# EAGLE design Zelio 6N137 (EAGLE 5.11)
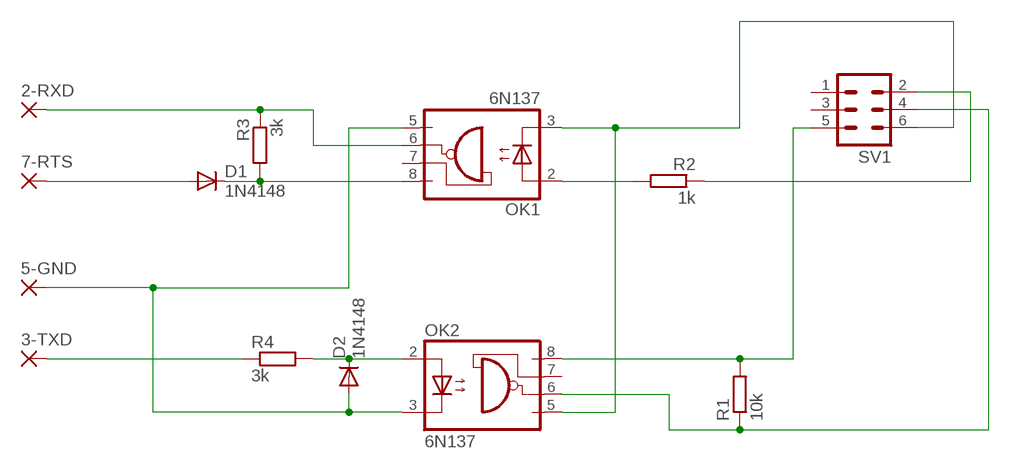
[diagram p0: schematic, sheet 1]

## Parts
2-RXD  2,54/1,0  [2,54/1,0]
3-TXD  2,54/1,0  [2,54/1,0]
5-GND  2,54/1,0  [2,54/1,0]
7-RTS  2,54/1,0  [2,54/1,0]
D1  1N4148  1N4148DO35-7  [DO35-7]
D2  1N4148  1N4148DO35-7  [DO35-7]
OK1  6N137  [DIL08]
OK2  6N137  [DIL08]
R1  10k  R-EU_0204/7  [0204/7]
R2  1k  R-EU_0204/7  [0204/7]
R3  3k  R-EU_0204/7  [0204/7]
R4  3k  R-EU_0204/7  [0204/7]
SV1  MA03-2  [MA03-2]

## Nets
N$1: OK2.8(VCC) R1.2 SV1.5
N$2: 3-TXD.1(P) R4.1
N$3: D2.C OK2.2(A) R4.2
N$4: 5-GND.1(P) D2.A OK1.5(GND) OK2.3(C)
N$5: 2-RXD.1(P) OK1.6(VO) R3.1
N$6: 7-RTS.1(P) D1.A
N$7: D1.C OK1.8(VCC) R3.2
N$8: OK1.2(A) R2.2
N$9: OK2.6(VO) R1.1 SV1.4
N$10: OK1.3(C) OK2.5(GND) SV1.6
N$11: R2.1 SV1.2
Unconnected: OK1.7(VE) OK2.7(VE) SV1.1 SV1.3

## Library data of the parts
2-RXD 3-TXD 5-GND 7-RTS = wirepad:2,54/1,0: THROUGH-HOLE PAD
D1 D2 = diode:1N4148: DIODE
OK1 OK2 = optocoupler:6N137: MOTOROLA OPTO COUPLER; MPN: 6N137; OC_FARNELL: 1328376; OC_NEWARK: 52M1895
R1-R4 = rcl:R-EU_: RESISTOR, European symbol
SV1 = con-lstb:MA03-2: PIN HEADER; OC_FARNELL: unknown; OC_NEWARK: unknown

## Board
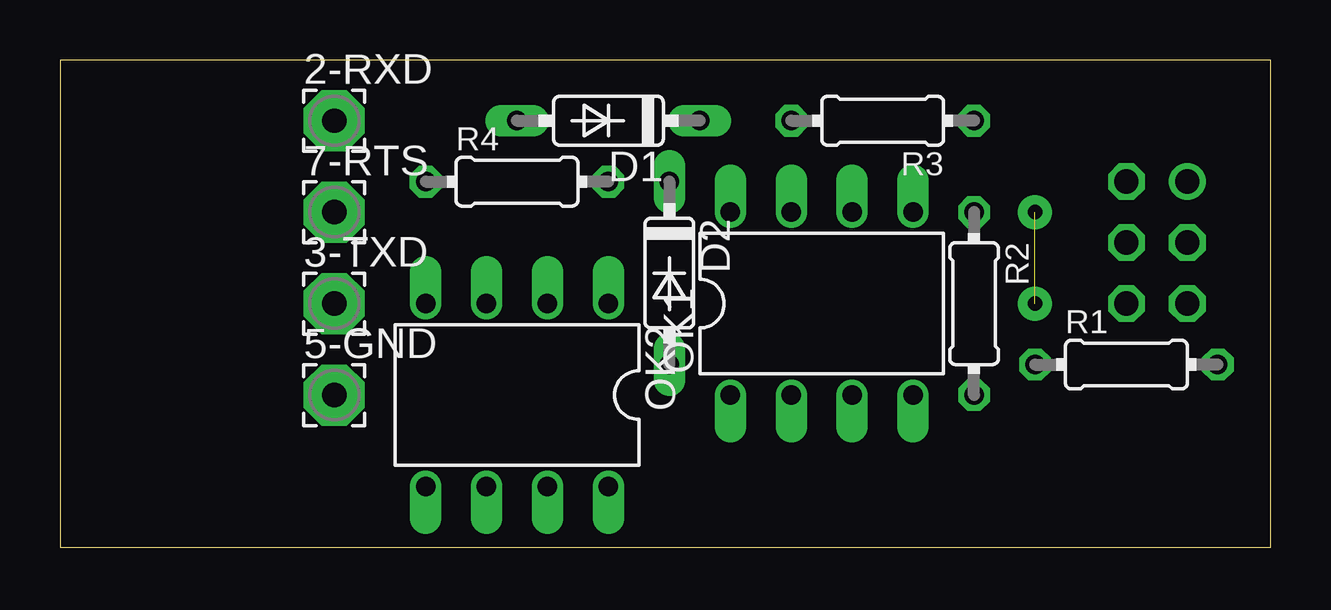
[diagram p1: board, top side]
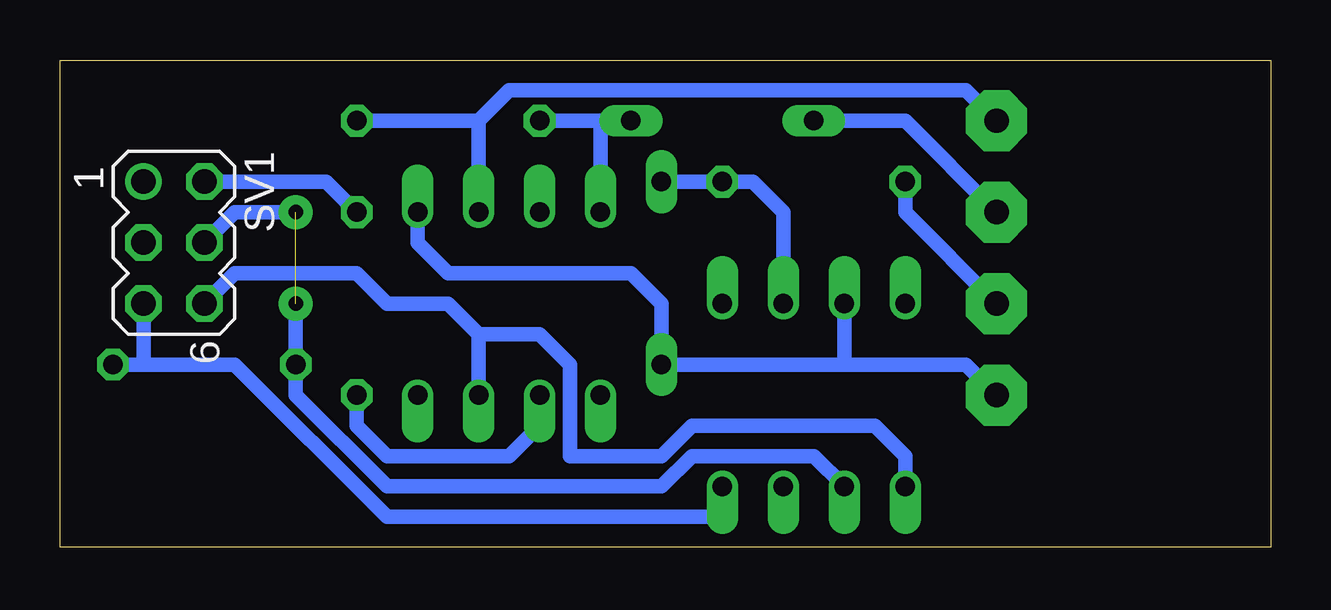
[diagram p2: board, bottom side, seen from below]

Size 50.47 x 20.31 mm. Coordinates in mm from the lower left corner, seen from the top.
Outline: 0,0 50.47,0 50.47,20.31 0,20.31 0,0
Copper layers (1*16): Top 0.035mm / dielectric 1.5mm / Bottom 0.035mm
Design rules "default": minimum track width 10mil, minimum drill 24mil, track to track 8mil, track to pad 8mil, pad to pad 8mil, via to via 8mil, smd to smd 8mil, copper to edge 40mil, drill to drill 8mil, minimum pad ring 10mil, minimum via ring 8mil, stop-mask expansion 4mil, vias tented up to drill 0mil, thermal gap 10mil

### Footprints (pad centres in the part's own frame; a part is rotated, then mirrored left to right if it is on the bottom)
2,54/1,0 = drill 1.016 pad 2.54 octagon: 1 0,0
DO35-7 = drill 0.813 long: A 3.81,0; C -3.81,0
DIL08 = drill 0.813 offset: 1 -3.81,-3.81; 2 -1.27,-3.81; 3 1.27,-3.81; 4 3.81,-3.81; 5 3.81,3.81; 6 1.27,3.81; 7 -1.27,3.81; 8 -3.81,3.81
0204/7 = drill 0.813 octagon: 1 -3.81,0; 2 3.81,0
MA03-2 = drill 1.016 round: 1 -2.54,-1.27 | drill 1.016 octagon: 2 -2.54,1.27; 3 0,-1.27; 4 0,1.27; 5 2.54,-1.27; 6 2.54,1.27

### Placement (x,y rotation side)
2-RXD  11.43,17.78 0 top
3-TXD  11.43,10.16 0 top
5-GND  11.43,6.35 0 top
7-RTS  11.43,13.97 0 top
D1  22.86,17.78 180 top
D2  25.4,11.43 270 top
OK1  31.75,10.16 0 top
OK2  19.05,6.35 180 top
R1  44.45,7.62 0 top
R2  38.1,10.16 270 top
R3  34.29,17.78 180 top
R4  19.05,15.24 0 top
SV1  45.72,12.7 270 bottom

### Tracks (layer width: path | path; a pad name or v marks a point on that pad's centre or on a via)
N$1
  Bottom 0.61: 46.99,7.62 R1.2 | 46.99,7.62 SV1.5 | 46.99,7.62 43.18,7.62 36.83,1.27 22.86,1.27 OK2.8
N$2
  Bottom 0.61: R4.1 15.24,13.97 3-TXD.1
N$3
  Bottom 0.61: D2.C R4.2 21.59,15.24 20.32,13.97 OK2.2
N$4
  Bottom 0.61: OK1.5 35.56,12.7 34.29,11.43 26.67,11.43 25.4,10.16 D2.A 17.78,7.62 | 17.78,7.62 OK2.3 | 5-GND.1 12.7,7.62 17.78,7.62
N$5
  Bottom 0.61: 33.02,17.78 OK1.6 | 33.02,17.78 31.75,19.05 12.7,19.05 2-RXD.1 | 33.02,17.78 R3.1
N$6
  Bottom 0.61: 7-RTS.1 15.24,17.78 D1.A
N$7
  Bottom 0.61: 27.94,17.78 D1.C | 27.94,17.78 R3.2 | OK1.8 27.94,17.78
N$8
  Bottom 0.61: OK1.2 30.48,5.08 31.75,3.81 36.83,3.81 38.1,5.08 R2.2
N$9  (1 unrouted)
  Bottom 0.61: SV1.4 43.18,13.97 40.64,13.97 | 40.64,10.16 R1.1 40.64,6.35 36.83,2.54 25.4,2.54 24.13,3.81 19.05,3.81 OK2.6
N$10
  Bottom 0.61: 33.02,8.89 OK1.3 | SV1.6 43.18,11.43 38.1,11.43 36.83,10.16 34.29,10.16 33.02,8.89 | 33.02,8.89 30.48,8.89 29.21,7.62 29.21,3.81 25.4,3.81 24.13,5.08 16.51,5.08 15.24,3.81 OK2.5
N$11
  Bottom 0.61: SV1.2 39.37,15.24 R2.1
N$12  (via drill 0.6 pad 1.42)
  other vias: 40.64,13.97
N$13  (via drill 0.6 pad 1.42)
  other vias: 40.64,10.16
